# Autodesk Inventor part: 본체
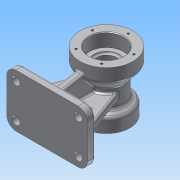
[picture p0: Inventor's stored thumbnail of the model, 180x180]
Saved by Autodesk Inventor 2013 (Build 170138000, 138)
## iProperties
Created: 2015-08
Part Number: 본체
Material: 알루미늄 6061
Document SubType Name: Modeling
Designer: Administrator
Density: 2.71 g/cm^3
Mass: 1062.79 g
Surface Area: 749.651 cm^2
Volume: 392.172 cm^3
Author: Administrator
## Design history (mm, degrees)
sketch "스케치1"
  geometry: L1 (0, 0)-(0, -90); L2 (0, 0)-(40, 0); L3 (40, 0)-(40, -20); L4 (40, -20)-(26, -36.685); L5 (26, -36.685)-(26, -64.804); L6 (26, -64.804)-(35, -70); L7 (35, -70)-(35, -90); L8 (35, -90)-(0, -90); 1 further point
  constraints: 16 end point, 3 perpendicular, 2 parallel, 1 coincident, 1 vertical
  dimensions: "d9" = 90 distance of L1.start L1.end; "d10" = 70 diameter of L7 L1; "d11" = 52 diameter of L5 L1; "d12" = 80 diameter of L3 L1; "d13" = 20 distance of L2.end L3.end; "d14" = 20 distance of L6.end L7.end; "d15" = 40 deg angle of L3 L4; "d16" = 60 deg angle of L7 L6
revolve "회전1" sketch "스케치1" stored, may be unused: angle "d17" = 90 deg
sketch "스케치2"
  geometry: L1 (-40, 0)-(40, 0) reference; L2 (40, 0)-(40, -20) reference; L3 (40, -20)-(26, -36.685) reference; L4 (26, -36.685)-(26, -64.804) reference; L5 (26, -64.804)-(35, -70) reference; L6 (35, -70)-(35, -90) reference; L7 (35, -90)-(-35, -90) reference; L8 (-35, -90)-(-35, -70) reference; L9 (-35, -70)-(-26, -64.804) reference; L10 (-26, -64.804)-(-26, -36.685) reference; L11 (-26, -36.685)-(-40, -20) reference; L12 (-40, -20)-(-40, 0) reference; L13 (-78, -90)-(-90, -90); L14 (-90, -90)-(-90, -10); L15 (-90, -10)-(-78, -10); L16 (-78, -10)-(-78, -90); 1 further point
  constraints: 8 end point, 2 parallel, 1 collinear, 1 horizontal, 1 perpendicular
  dimensions: "d18" = 12 distance of L14.end L15.end; "d19" = 80 distance of L13.end L14.end; "d20" = 90 distance from line of point (0, 0) L14
extrude "돌출1" join sketch "스케치2" stored distance "d21" = 122; taper "d22" = 0 deg
fillet "모깎기4" dims "d98" = 5
sketch "스케치3"
  geometry: L1 (-40, 0)-(40, 0) reference; L2 (40, 0)-(40, -18.18) reference; L3 (35, -72.887)-(35, -90) reference; L4 (35, -90)-(-35, -90) reference; L5 (-35, -90)-(-35, -72.887) reference; L6 (-40, -18.18)-(-40, 0) reference; L7 (-90, -90)-(-90, -10) reference; L8 (-90, -10)-(-78, -10) reference; L9 (-78, -10)-(-78, -90) reference; L10 (-78, -90)-(-90, -90) reference; L11 (-35, -80)-(-78, -80); L12 (-40, -13.3)-(-78, -20); L13 (38.83, -21.394)-(27.17, -35.29) reference; L14 (26, -38.504)-(26, -61.917) reference; L15 (28.5, -66.247)-(32.5, -68.557) reference; L16 (-32.5, -68.557)-(-28.5, -66.247) reference; L17 (-26, -61.917)-(-26, -38.504) reference; L18 (-27.17, -35.29)-(-38.83, -21.394) reference; L19 (-22.763, -10.26)-(-22.763, -80); L20 (-40, -13.3)-(-22.763, -10.26); L21 (-35, -80)-(-22.763, -80); A1 r 5 centre (35, -18.18) between (38.83, -21.394) and (40, -18.18) reference; A2 r 5 centre (31, -38.504) between (27.17, -35.29) and (26, -38.504) reference; A3 r 5 centre (31, -61.917) between (26, -61.917) and (28.5, -66.247) reference; A4 r 5 centre (30, -72.887) between (35, -72.887) and (32.5, -68.557) reference; A5 r 5 centre (-30, -72.887) between (-32.5, -68.557) and (-35, -72.887) reference; A6 r 5 centre (-31, -61.917) between (-28.5, -66.247) and (-26, -61.917) reference; A7 r 5 centre (-31, -38.504) between (-26, -38.504) and (-27.17, -35.29) reference; A8 r 5 centre (-35, -18.18) between (-40, -18.18) and (-38.83, -21.394) reference; 1 further point
  constraints: 10 end point, 4 point on line, 2 parallel, 1 collinear, 1 perpendicular
  dimensions: "d23" = 10 distance between parallel lines of L11 L10; "d24" = 10 distance from line of L8 L12.end; "d25" = 80 deg angle of L9 L12; "d99" = 69.73972 distance of L19.start L19.end
extrude "돌출4" join sketch "스케치3" stored distance "d100" = 12; taper "d101" = 0 deg
node "작업 평면1"
sketch "스케치4"
  geometry: L1 (0, 0)-(0, 12) reference; L2 (0, 12)-(55, 12) reference; L3 (67, 12)-(122, 12) reference; L4 (122, 12)-(122, 0) reference; L5 (122, 0)-(0, 0) reference; L6 (112, 12)-(86.091, 83.185); L7 (55, 12)-(55, 64.702) reference; L8 (67, 64.702)-(67, 12) reference; A1 r 26 centre (61, 90) between (67, 64.702) and (55, 64.702) reference; 1 further point
  constraints: 2 end point, 1 point on circle, 1 point on line
  dimensions: "d29" = 10 distance from line of L4 L6.start; "d30" = 70 deg angle of L3 L6
feature "리브1" sketch "스케치4" dims "d31" = 1, "d32" = 12, "d33" = 0, "d34" = 0, "d35" = 1, "d36" = 1
fillet "모깎기1" dims "d37" = 14
sketch "스케치5"
  geometry: A1 r 14 centre (0, 66) between (0, 80) and (-14, 66) reference; A2 r 14 centre (0, 14) between (-14, 14) and (0, 0) reference; A3 r 14 centre (94, 14) between (94, 0) and (108, 14) reference; A4 r 14 centre (94, 66) between (108, 66) and (94, 80) reference; 5 further points
  constraints: 4 coincident
hole "구멍1" sketch "스케치5" at (0, 66), (94, 66), (94, 14), (0, 14) diameter "d38" = 12; stored, may be unused: countersink angle "d42" = 90 deg, drill point angle "d44" = 0 deg; dims "d39" = 6, "d40" = 4, "d41" = 2, "d43" = 8
hole "구멍2" diameter "d47" = 38; stored, may be unused: countersink angle "d51" = 90 deg, drill point angle "d53" = 0 deg; dims "d45" = 10, "d46" = 10, "d48" = 6, "d49" = 52, "d50" = 20, "d52" = 23
hole "구멍3" diameter "d56" = 32; stored, may be unused: countersink angle "d60" = 90 deg, drill point angle "d62" = 0 deg; dims "d54" = 10, "d55" = 10, "d57" = 6, "d58" = 40, "d59" = 17, "d61" = 23
sketch "스케치6"
  geometry: C1 r 20 at (0, 0) reference; 1 further point
  constraints: 1 vertical alignment
  dimensions: "d63" = 27 distance of C1.centre point (0, 27)
hole "구멍4" sketch "스케치6" at (0, 27) diameter "d64" = 3.242; stored, may be unused: countersink angle "d68" = 90 deg, drill point angle "d70" = 118 deg; dims "d65" = 10, "d66" = 40, "d67" = 17, "d69" = 13
sketch "스케치7"
  geometry: C1 r 26 at (0, 0) reference; 1 further point
  constraints: 1 vertical alignment
  dimensions: "d74" = 33 distance of C1.centre point (0, 33)
hole "구멍5" sketch "스케치7" at (0, 33) diameter "d75" = 3.242; stored, may be unused: countersink angle "d79" = 90 deg, drill point angle "d81" = 118 deg; dims "d76" = 10, "d77" = 40, "d78" = 17, "d80" = 13
sketch "스케치8"
  geometry: L1 (21, 24)-(21, 18); L2 (33, 24)-(33, 18); L3 (-10, 0)-(4, 0) reference; A1 r 26 centre (51, 78) between (25.909, 71.185) and (45, 52.702) reference; A2 r 6 centre (27, 24) between (33, 24) and (21, 24); A3 r 6 centre (27, 18) between (21, 18) and (33, 18); 1 further point
  constraints: 4 end point, 4 point on circle, 3 tangent, 2 centre point, 1 parallel, 1 vertical alignment
  dimensions: "d85" = 12 diameter of A2; "d86" = 12 diameter of A3; "d87" = 18 dimension on A3 A2; "d89" = 18 distance from line of A3.centre L3; "d102" = 24 horizontal distance of A1.centre A3.centre
extrude "돌출3" cut sketch "스케치8" distance "d90" = 12; taper "d91" = 0 deg
chamfer "모따기1" distance "d92" = 1; stored, may be unused: second distance "d93" = 2, angle "d94" = 45 deg
fillet "모깎기2" dims "d95" = 0.3, "d96" = 3
fillet "모깎기3" dims "d97" = 3
fillet "모깎기5" dims "d103" = 3
fillet "모깎기6" dims "d104" = 3
fillet "모깎기7" dims "d105" = 3
sketch "스케치10"
  geometry: L1 (-24, -78)-(-76, -78) reference; L2 (-80, -37.881)-(-80, -75) reference; 2 further points
  constraints: 1 other
  dimensions: "d106" = 24 distance from line of point (-64, -54) L1; "d107" = 16 distance from line of point (-64, -54) L2
feature "엠보싱1" sketch "스케치10" dims "d9" = 90, "d10" = 70, "d11" = 52, "d12" = 80, "d13" = 20, "d14" = 20, "d15" = 40 deg, "d16" = 60 deg, "d108" = 0.5, "d109" = 0
node "솔리드1"
mirror "대칭1"
pattern_circular "원형 패턴1" dims angle "d72" = 360 deg
pattern_circular "원형 패턴2" dims angle "d83" = 360 deg
mirror "대칭2"
node "절단 모서리 투영1"
node "절단 모서리 투영2"
node "절단 모서리 투영3"
